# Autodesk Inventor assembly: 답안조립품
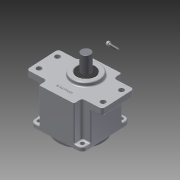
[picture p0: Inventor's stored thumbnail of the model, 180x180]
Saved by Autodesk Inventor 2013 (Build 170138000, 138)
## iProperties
Created: 2015-07
Part Number: 답안조립품
Document SubType Name: Assembly
Designer: user
Author: user
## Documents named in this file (12)
- C:\Users\user\Desktop\450734V1025\답안조립품.iam
- C:\Users\user\Desktop\450734V1025\메인축.ipt
- C:\Users\user\Desktop\450734V1025\베어링 6003.ipt
- 베어링 6003.ipt
- C:\Users\user\Desktop\450734V1025\베어링 608.ipt
- 베어링 608.ipt
- C:\Users\user\Desktop\450734V1025\서브축.ipt
- C:\Users\user\Desktop\450734V1025\본체.ipt
- C:\Users\user\Desktop\450734V1025\커버.ipt
- C:\Users\user\Desktop\450734V1025\오일실 8x22x7.ipt
- C:\Users\user\Desktop\450734V1025\오일실 17x32x8.ipt
- C:\Users\user\Desktop\450734V1025\M4x0.5x16.ipt
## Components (9 placed, 1 different names)
1. M4x0.5x12:6
2. M4x0.5x12:1
3. M4x0.5x12:2
4. M4x0.5x12:3
5. M4x0.5x12:4
6. M4x0.5x12:5
7. M4x0.5x12:7
8. M4x0.5x12:8
9. M4x0.5x12:9
